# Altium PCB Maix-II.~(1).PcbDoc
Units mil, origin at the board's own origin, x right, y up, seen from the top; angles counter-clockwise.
Board outline 6000 x 4000 mil, 2 copper layers (Top Layer, Bottom Layer); 2 components, 0 nets, 72 pads, 0 vias.
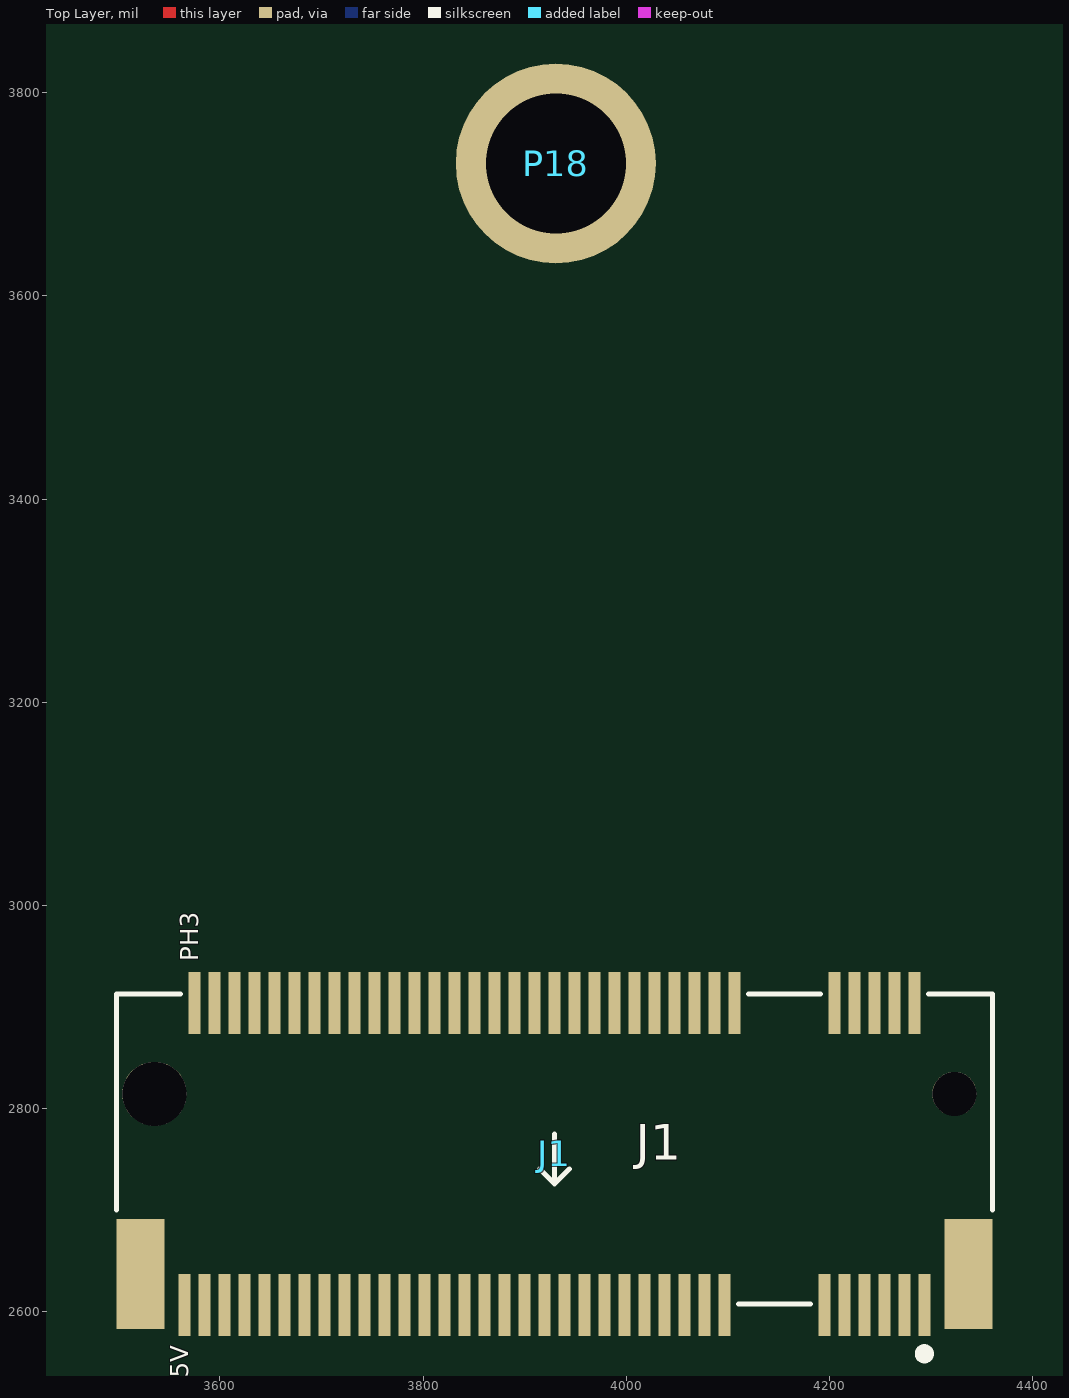
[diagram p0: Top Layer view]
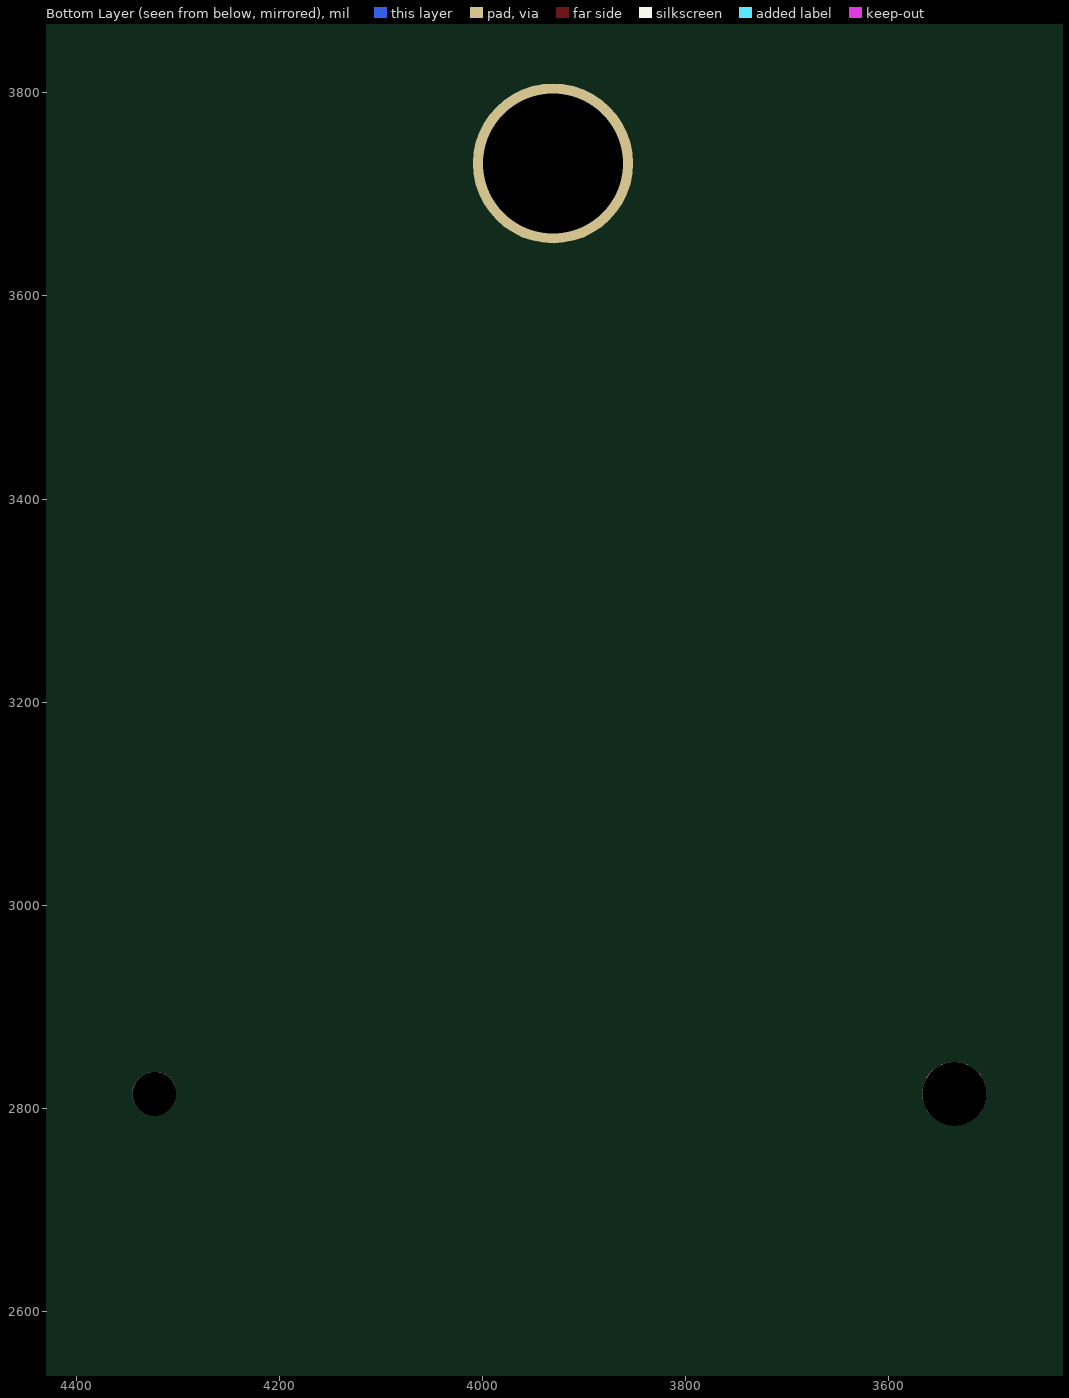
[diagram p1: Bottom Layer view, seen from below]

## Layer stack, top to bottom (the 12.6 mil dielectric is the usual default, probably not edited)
Top Solder: solder mask 0.4, Solder Resist, Dk 3.5
Top Layer: signal copper 1.4
Dielectric 1: dielectric 12.6, FR-4, Dk 4.8
Bottom Layer: signal copper 1.4
Bottom Solder: solder mask 0.4, Solder Resist, Dk 3.5

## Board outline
1000,1000 7000,1000 7000,5000 1000,5000

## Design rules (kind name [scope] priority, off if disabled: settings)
Clearance [All] p1: gap=10 ignorepadtopadclearanceinfootprint=FALSE except(0: Arc-Hole Track-Hole SMDPad-Hole THPad-Hole Via-Hole Fill-Hole Poly-Hole Region-Hole Text-Hole)
PolygonConnect [All] p1: connectstyle=Relief reliefconductorwidth=10 reliefentries=4 polygonreliefangle="90 Angle" airgapwidth=10
RoutingVias [All] p1: holewidth=28 width=50 viastyle="Through Hole" minholewidth=28 minwidth=50 maxholewidth=28 maxwidth=50
SolderMaskExpansion [All] p1: expansion=4 istentingtop=FALSE
Width [All] p1: maxlimit=10 minlimit=10 preferedwidth=10
30 further rules are at their usual default settings.

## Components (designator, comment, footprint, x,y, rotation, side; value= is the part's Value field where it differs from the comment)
J1 "NGFF-67P_B-KEY座子 4.2H高" M2-67P0R50_B_FEMALE 3929.31,2814.68 r180 top
P18 "M2x4.5x4.2 铜柱2.6H 贴片螺母" "M.2 SMT-FEMALE - FULL" 3930.69,3730.42 r0 top

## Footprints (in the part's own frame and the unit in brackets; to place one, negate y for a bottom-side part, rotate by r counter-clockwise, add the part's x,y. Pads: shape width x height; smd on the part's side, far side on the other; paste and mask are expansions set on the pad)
M2-67P0R50_B_FEMALE [mm] "M2-67P0R50_B"
  rect 0.3x1.55 smd mask+0.051: 1(-9.25,5.275) 2(-9,-2.275) 3(-8.75,5.275) 4(-8.5,-2.275) 5(-8.25,5.275) 6(-8,-2.275) 7(-7.75,5.275) 8(-7.5,-2.275) 9(-7.25,5.275) 10(-7,-2.275) 11(-6.75,5.275) 20(-4.5,-2.275) 21(-4.25,5.275) 22(-4,-2.275) 23(-3.75,5.275) 24(-3.5,-2.275) 25(-3.25,5.275) 26(-3,-2.275) 27(-2.75,5.275) 28(-2.5,-2.275) 29(-2.25,5.275) 30(-2,-2.275) 31(-1.75,5.275) 32(-1.5,-2.275) 33(-1.25,5.275) 34(-1,-2.275) 35(-0.75,5.275) 36(-0.5,-2.275) 37(-0.25,5.275) 38(0,-2.275) 39(0.25,5.275) 40(0.5,-2.275) 41(0.75,5.275) 42(1,-2.275) 43(1.25,5.275) 44(1.5,-2.275) 45(1.75,5.275) 46(2,-2.275) 47(2.25,5.275) 48(2.5,-2.275) 49(2.75,5.275) 50(3,-2.275) 51(3.25,5.275) 52(3.5,-2.275) 53(3.75,5.275) 54(4,-2.275) 55(4.25,5.275) 56(4.5,-2.275) 57(4.75,5.275) 58(5,-2.275) 59(5.25,5.275) 60(5.5,-2.275) 61(5.75,5.275) 62(6,-2.275) 63(6.25,5.275) 64(6.5,-2.275) 65(6.75,5.275) 66(7,-2.275) 67(7.25,5.275) 68(7.5,-2.275) 69(7.75,5.275) 70(8,-2.275) 71(8.25,5.275) 72(8.5,-2.275) 73(8.75,5.275) 74(9,-2.275) 75(9.25,5.275)
  round 1.1 hole 1.1 mask+0.051: " "(-10,0)
  round 1.6 / inner round 1.524 / far side round 1.6 hole 1.6 mask+0.051: " "(10,0)
  rect 1.2x2.75 smd mask+0.051: SH1(-10.35,4.5) SH2(10.35,4.5)
  silkscreen extent -10.95,-2.5 10.95,6.62, body extent -10.95,-2.85 10.95,5.85, height 4.09
"M.2 SMT-FEMALE - FULL" [mm]
  round 5 / inner round 4 / far side round 4 hole 3.5 paste+0 mask+0.051: 1(0,0)
  body extent -2.26,-2.24 2.24,2.26, height 2.46

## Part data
J1: library part NGFF-67P_B-MALE
P18: library part HEADER-1X1

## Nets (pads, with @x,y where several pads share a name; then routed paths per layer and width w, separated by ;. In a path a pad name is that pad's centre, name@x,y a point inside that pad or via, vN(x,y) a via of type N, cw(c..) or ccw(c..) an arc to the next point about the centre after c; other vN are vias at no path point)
pads on no net: "J1. " J1.1 J1.2 J1.3 J1.4 J1.5 J1.6 J1.7 J1.8 J1.9 J1.10 J1.11 J1.20 J1.21 J1.22 J1.23 J1.24 J1.25 J1.26 J1.27 J1.28 J1.29 J1.30 J1.31 J1.32 J1.33 J1.34 J1.35 J1.36 J1.37 J1.38 J1.39 J1.40 J1.41 J1.42 J1.43 J1.44 J1.45 J1.46 J1.47 J1.48 J1.49 J1.50 J1.51 J1.52 J1.53 J1.54 J1.55 J1.56 J1.57 J1.58 J1.59 J1.60 J1.61 J1.62 J1.63 J1.64 J1.65 J1.66 J1.67 J1.68 J1.69 J1.70 J1.71 J1.72 J1.73 J1.74 J1.75 J1.SH1 J1.SH2 P18.1

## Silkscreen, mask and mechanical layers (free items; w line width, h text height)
Top Overlay:
  text "PH3" at 3584.67,2945 h30 r90
  text "5V" at 3574.67,2535 h30 r90
  text "AP-RESET" at 4304.67,2400 h30 r90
